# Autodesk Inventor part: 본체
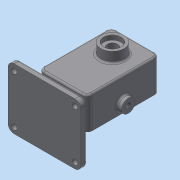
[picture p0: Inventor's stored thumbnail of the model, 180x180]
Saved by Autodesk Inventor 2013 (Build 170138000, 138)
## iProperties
Created: 2020-04
Part Number: 본체
Material: 일반
Document SubType Name: Modeling
Designer: dgall
Density: 1 g/cm^3
Author: dgall
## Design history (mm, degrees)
sketch "스케치1"
  geometry: L1 (-40, 60)-(40, 60); L2 (40, 60)-(40, -60); L3 (40, -60)-(-40, -60); L4 (-40, -60)-(-40, 60); 1 further point
  constraints: 8 end point, 2 parallel, 1 horizontal, 1 perpendicular
  dimensions: "d0" = 80 distance of L1.start L1.end; "d2" = 120 distance of L3.end L1.start; "d3" = 40 distance from line of L4 point (0, 0); "d4" = 60 distance from line of point (0, 0) L1
extrude "돌출1" new body sketch "스케치1" stored distance "d5" = 53; taper "d6" = 0 deg
fillet "모깎기1" dims "d7" = 9
node "작업 평면1"
sketch "스케치2"
  geometry: C1 r 19 at (0, 22); 1 further point
  constraints: 1 centre point, 1 vertical alignment
  dimensions: "d9" = 22 distance of point (0, 0) C1.centre; "d10" = 38 diameter of C1
extrude "돌출2" join sketch "스케치2" stored distance "d11" = 38 (= d10); taper "d12" = 0 deg
sketch "스케치3"
  geometry: L1 (-31, -60)-(31, -60) reference; L2 (-24, 22)-(-24, -22); L3 (24, 22)-(24, -22); A1 r 24 centre (0, 22) between (24, 22) and (-24, 22); A2 r 24 centre (0, -22) between (-24, -22) and (24, -22); 1 further point
  constraints: 4 end point, 4 point on circle, 2 centre point, 2 tangent, 2 vertical alignment, 1 parallel, 1 perpendicular
  dimensions: "d13" = 48 diameter of A1; "d16" = 48 diameter of A2; "d17" = 44 distance of A2.centre A1.centre; "d18" = 22 distance of point (0, 0) A1.centre
extrude "돌출3" cut sketch "스케치3" distance "d19" = 29; taper "d20" = 0 deg
sketch "스케치4"
  geometry: C1 r 12.5 at (0, 22); C2 r 12.5 at (0, -22); A1 r 24 centre (0, 22) between (24, 22) and (-24, 22) reference; A2 r 24 centre (0, -22) between (-24, -22) and (24, -22) reference; 1 further point
  constraints: 2 centre point, 2 coincident
  dimensions: "d21" = 25 diameter of C1; "d23" = 25 diameter of C2
extrude "돌출4" cut sketch "스케치4" distance "d24" = 15; taper "d25" = 0 deg
hole "구멍1" diameter "d28" = 17; stored, may be unused: countersink angle "d32" = 90 deg, drill point angle "d34" = 0 deg; dims "d26" = 10, "d27" = 10, "d29" = 6, "d30" = 28, "d31" = 7.3, "d33" = 8
sketch "스케치6" dims "d114" = 20
  geometry: L1 (8, 43.5)-(36, 43.5) reference; L2 (36, 36.2)-(36, 43.5) reference; L3 (22, 42.8)-(36, 42.8); L4 (3, 43.5)-(41, 43.5) reference; L5 (36, 42.8)-(36.404, 43.5); L6 (22, 42.8)-(22, 43.5); 1 further point
  constraints: 6 end point, 2 point on line, 1 midpoint, 1 parallel
  dimensions: "d35" = 0.7 distance between parallel lines of L1 L3; "d36" = 30 deg angle of L2 L5; "d37" = 0.7 distance of L3.start L6.end
revolve "회전1" sketch "스케치6" stored, may be unused: angle "d38" = 90 deg
node "작업 평면2"
sketch "스케치11"
  geometry: L1 (51, -26.5)-(-51, -26.5) reference; C1 r 11 at (0, -12.5); 1 further point
  constraints: 1 centre point, 1 vertical alignment
  dimensions: "d59" = 22 diameter of C1; "d61" = 14 distance from line of C1.centre L1
extrude "돌출6" join sketch "스케치11" stored distance "d62" = 15; taper "d63" = 0 deg
hole "구멍3" diameter "d66" = 8.376; stored, may be unused: countersink angle "d70" = 90 deg, drill point angle "d72" = 0 deg; dims "d64" = 10, "d65" = 10, "d67" = 6, "d68" = 28, "d69" = 7.3, "d71" = 8
sketch "스케치12"
  geometry: L1 (-80, -56.5)-(-90, -56.5); L2 (-90, -56.5)-(-90, 43.5); L3 (-90, 43.5)-(-80, 43.5); L4 (-80, 43.5)-(-80, -56.5); L5 (3, 43.5)-(41, 43.5) reference; 1 further point
  constraints: 8 end point, 2 parallel, 1 horizontal, 1 horizontal alignment, 1 perpendicular
  dimensions: "d73" = 100 distance of L3.end L1.start; "d75" = 10 distance of L2.end L3.end; "d76" = 90 distance from line of L2 point (0, 0)
extrude "돌출7" join sketch "스케치12" stored distance "d77" = 120; taper "d78" = 0 deg
sketch "스케치13"
  geometry: L1 (24, -54.052)-(24, -86.78); L2 (-24, -54.052)-(-24, -86.78); L3 (24, -54.052)-(-24.009, -54.052); L4 (24, -86.78)-(-24, -86.78); 1 further point
  constraints: 8 end point, 2 parallel, 1 horizontal, 1 point on line, 1 vertical
  dimensions: "d79" = 48 distance between parallel lines of L2 L1; "d81" = 24 distance from line of L1 point (0, 0)
extrude "돌출8" join sketch "스케치13" stored distance "d82" = 53; taper "d83" = 0 deg
sketch "스케치14"
  geometry: L1 (-80, -56.5)-(-80, 43.5) reference; L2 (-60, -26.5)-(-80, -26.5) reference; L3 (-80, 26.5)-(-60, 26.5) reference; L4 (-60, 26.5)-(-60, -26.5) reference; L5 (-80, -26.5)-(-60, -14.953); L6 (-60, -14.953)-(-60, -26.5); L7 (-80, -26.5)-(-60, -26.5); 1 further point
  constraints: 6 end point, 2 collinear, 1 point on line
  dimensions: "d84" = 60 deg angle of L1 L5
extrude "돌출9" cut sketch "스케치14" stored distance "d85" = 53; taper "d86" = 0 deg
fillet "모깎기2" dims "d87" = 3
fillet "모깎기3" dims "d88" = 3
fillet "모깎기4" dims "d89" = 10
sketch "스케치17"
  geometry: C1 r 4.5 at (100, 90); A1 r 10 centre (100, 90) between (110, 90) and (100, 100) reference; 1 further point
  constraints: 1 centre point, 1 coincident
  dimensions: "d90" = 9 diameter of C1
extrude "돌출10" cut sketch "스케치17" distance "d92" = 53; taper "d93" = 0 deg
sketch "스케치18"
  geometry: C1 r 4.5 at (100, 10); A1 r 10 centre (100, 10) between (100, 0) and (110, 10) reference; 1 further point
  constraints: 1 centre point, 1 coincident
  dimensions: "d94" = 9 diameter of C1
extrude "돌출11" cut sketch "스케치18" distance "d96" = 53; taper "d97" = 0 deg
fillet "모깎기5" dims "d98" = 3
fillet "모깎기6" dims "d99" = 3
fillet "모깎기7" dims "d100" = 3
fillet "모깎기9" dims "d102" = 0.5
chamfer "모따기1" distance "d103" = 1; stored, may be unused: second distance "d104" = 2, angle "d105" = 45 deg
fillet "모깎기10" dims "d106" = 3
sketch "스케치20"
  geometry: A1 r 9 centre (-31, 51) between (-31, 60) and (-40, 51) reference; 2 further points
  constraints: 1 coincident
hole "구멍4" sketch "스케치20" at (-31, 51) diameter "d107" = 4.134; stored, may be unused: countersink angle "d111" = 90 deg, drill point angle "d113" = 118 deg; dims "d108" = 10, "d109" = 28, "d110" = 7.3, "d112" = 12
sketch "스케치21"
  geometry: L1 (110, -87)-(110, -7) reference; L2 (100, 3)-(0, 3) reference; 2 further points
  constraints: 1 other
  dimensions: "d123" = 60 distance from line of L1 point (50, -7); "d124" = 10 distance from line of L2 point (50, -7)
feature "엠보싱1" sketch "스케치21" dims "d125" = 0.5, "d126" = 0
node "솔리드1"
mirror "대칭2"
mirror "대칭3"
mirror "대칭4"
mirror "대칭5"
pattern_linear "직사각형 패턴1" dims "d116" = 62
pattern_linear "직사각형 패턴2" dims "d119" = 29
pattern_linear "직사각형 패턴3" dims "d122" = 73
other parameters: "d8" = 43.5, "d39" = -48
